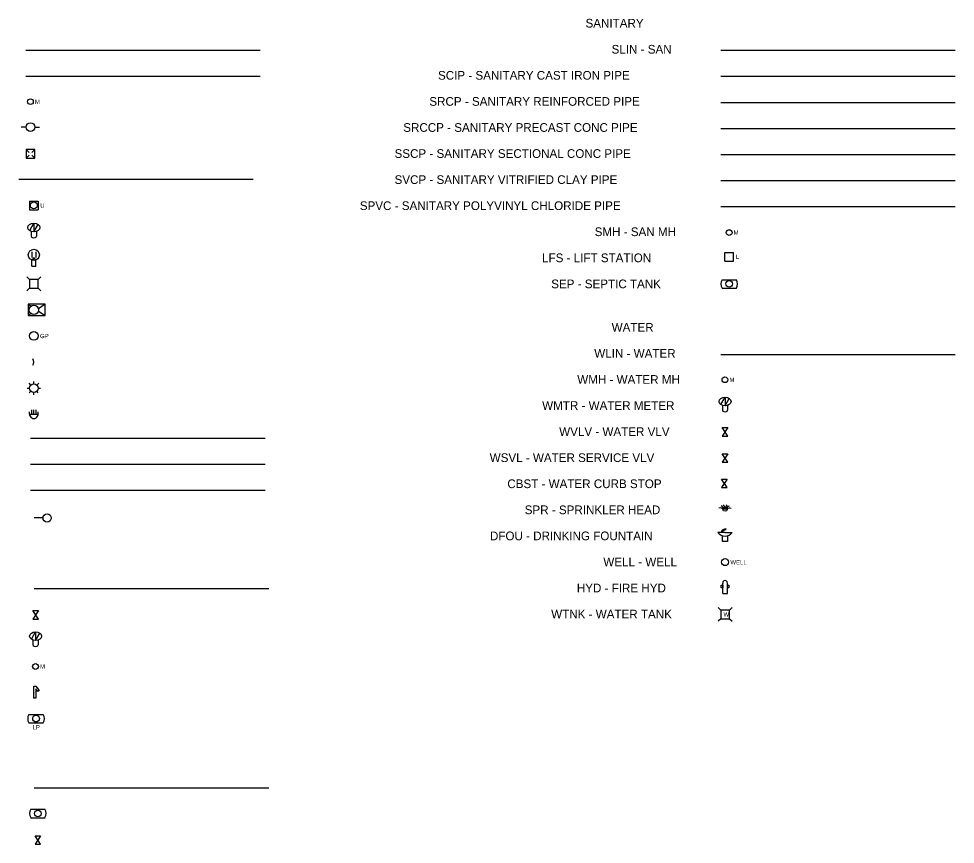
# Model space of a CAD drawing. Extents: x 2147097 to 2149342, y 2146141 to 2147624.
# Drawn here: x 2148264 to 2149342, y 2146471 to 2147421 of the extents above; entities that cross this region are included whole.
import ezdxf

# ---------------------------------------------------------------- set-up
doc = ezdxf.new("R2010")
doc.units = 0
for name, color, linetype in [('Default', 7, 'Continuous'), ('GAS LIN INP', 7, 'Continuous'), ('GAS PT INP', 7, 'Continuous'), ('PET LIN INP', 7, 'Continuous'), ('PET PT INP', 7, 'Continuous'), ('PWR LIN INP', 7, 'Continuous'), ('PWR LIN OVHD INP', 7, 'Continuous'), ('PWR PT INP', 7, 'Continuous'), ('SAN LIN INP', 7, 'Continuous'), ('SAN PT INP', 7, 'Continuous'), ('WTR LIN INP', 7, 'Continuous'), ('WTR PT INP', 7, 'Continuous')]:
    doc.layers.add(name, color=color, linetype=linetype)

msp = doc.modelspace()

# ---------------------------------------------------------------- linework, layer by layer
at = {"layer": 'GAS LIN INP'}
msp.add_line((2148281.3, 2146765.8), (2148551.3, 2146765.8), dxfattribs=at)
at = {"layer": 'GAS PT INP'}
for p, q in [((2148279.8, 2146740.3), (2148286.2, 2146740.3)), ((2148286.2, 2146730.5), (2148279.8, 2146740.3)), ((2148286.2, 2146740.3), (2148279.8, 2146730.5)), ((2148283, 2146735.4), (2148283, 2146735.4)), ((2148283, 2146735.4), (2148283, 2146735.4)), ((2148279.8, 2146730.5), (2148286.2, 2146730.5)), ((2148278.2, 2146707.5), (2148283, 2146715.8)), ((2148283, 2146715.8), (2148283, 2146706)), ((2148283, 2146706), (2148287.9, 2146714.4)), ((2148280, 2146706.5), (2148280, 2146700.9)), ((2148286, 2146706.5), (2148286, 2146700.9)), ((2148282, 2146646.2), (2148282, 2146646.2)), ((2148275.2, 2146620.8), (2148291.8, 2146620.8)), ((2148283.5, 2146616), (2148283.5, 2146616)), ((2148275.2, 2146611.1), (2148291.8, 2146611.1))]:
    msp.add_line(p, q, dxfattribs=at)
msp.add_lwpolyline([(2148281, 2146639.6), (2148281, 2146653.2), (2148283.4, 2146653.2), (2148287, 2146648.2), (2148285.5, 2146647.1), (2148283.2, 2146650.2), (2148283.2, 2146639.6)], close=True, dxfattribs=at)
for centre, radius in [((2148282.9, 2146676), 3.31), ((2148283.5, 2146616), 3.83)]:
    msp.add_circle(centre, radius, dxfattribs=at)
for centre, start, end in [((2148283, 2146616), 148.1092, 211.8908), ((2148284, 2146616), 328.1092, 31.8908)]:
    msp.add_arc(centre, 9.11, start, end, dxfattribs=at)
msp.add_ellipse((2148283, 2146710.9), major_axis=(-6.9, 0), ratio=0.710145, dxfattribs=at)
msp.add_ellipse((2148283, 2146700.9), major_axis=(-3, 0), ratio=0.602742, start_param=0, end_param=3.141593, dxfattribs=at)
at = {"layer": 'PET LIN INP'}
msp.add_line((2148281.5, 2146536.2), (2148551.5, 2146536.2), dxfattribs=at)
at = {"layer": 'PET PT INP'}
for p, q in [((2148277.3, 2146511.7), (2148293.9, 2146511.7)), ((2148285.6, 2146506.9), (2148285.6, 2146506.9)), ((2148277.3, 2146502), (2148293.9, 2146502)), ((2148282.4, 2146481.2), (2148288.8, 2146481.2)), ((2148288.8, 2146471.4), (2148282.4, 2146481.2)), ((2148288.8, 2146481.2), (2148282.4, 2146471.4)), ((2148285.6, 2146476.3), (2148285.6, 2146476.3)), ((2148285.6, 2146476.3), (2148285.6, 2146476.3)), ((2148282.4, 2146471.4), (2148288.8, 2146471.4))]:
    msp.add_line(p, q, dxfattribs=at)
msp.add_circle((2148285.6, 2146506.9), 3.83, dxfattribs=at)
for centre, start, end in [((2148285.1, 2146506.9), 148.1092, 211.8908), ((2148286.1, 2146506.9), 328.1092, 31.8908)]:
    msp.add_arc(centre, 9.11, start, end, dxfattribs=at)
at = {"layer": 'PWR LIN INP'}
for p, q in [((2148271.6, 2147385.2), (2148541.6, 2147385.2)), ((2148263.6, 2147236.8), (2148533.6, 2147236.8)), ((2148277.1, 2146938.9), (2148547.1, 2146938.9)), ((2148277.1, 2146908.9), (2148547.1, 2146908.9)), ((2148277.1, 2146878.9), (2148547.1, 2146878.9))]:
    msp.add_line(p, q, dxfattribs=at)
at = {"layer": 'PWR LIN OVHD INP'}
msp.add_line((2148271.6, 2147355.2), (2148541.6, 2147355.2), dxfattribs=at)
at = {"layer": 'PWR PT INP'}
for p, q in [((2148272.1, 2147296.8), (2148266.5, 2147296.8)), ((2148282.1, 2147296.8), (2148287.7, 2147296.8)), ((2148272.1, 2147270.9), (2148275.6, 2147267.4)), ((2148272.1, 2147260.9), (2148275.6, 2147264.4)), ((2148277.1, 2147265.9), (2148277.1, 2147265.9)), ((2148278.6, 2147267.4), (2148282.1, 2147270.9)), ((2148278.6, 2147264.4), (2148282.1, 2147260.9)), ((2148281, 2147206.6), (2148281, 2147206.6)), ((2148276.2, 2147177.9), (2148281, 2147186.2)), ((2148281, 2147186.2), (2148281, 2147176.4)), ((2148278, 2147176.9), (2148278, 2147171.3)), ((2148281, 2147176.4), (2148285.9, 2147184.8)), ((2148284, 2147176.9), (2148284, 2147171.3)), ((2148278.6, 2147153.3), (2148278.6, 2147146.5)), ((2148278.6, 2147136.7), (2148278.6, 2147143.8)), ((2148283.4, 2147153.3), (2148283.4, 2147146.5)), ((2148283.4, 2147136.7), (2148283.4, 2147143.8)), ((2148278.6, 2147136.7), (2148283.4, 2147136.7)), ((2148273, 2147124.4), (2148276, 2147121.4)), ((2148289, 2147124.4), (2148286, 2147121.4)), ((2148276, 2147111.4), (2148273, 2147108.4)), ((2148281, 2147116.4), (2148281, 2147116.4)), ((2148286, 2147111.4), (2148289, 2147108.4)), ((2148274.5, 2147092.9), (2148277.8, 2147090.7)), ((2148294, 2147092.9), (2148286.2, 2147087.7)), ((2148277.8, 2147082.1), (2148274.5, 2147079.9)), ((2148286.2, 2147085.1), (2148294, 2147079.9)), ((2148281, 2147001.4), (2148281, 2147004)), ((2148273.4, 2146996.4), (2148276, 2146996.4)), ((2148277.5, 2146999.9), (2148275.5, 2147002)), ((2148275.5, 2146990.8), (2148277.5, 2146992.9)), ((2148281, 2146996.4), (2148281, 2146996.4)), ((2148284.5, 2146999.9), (2148286.6, 2147002)), ((2148286.1, 2146990.8), (2148284.5, 2146992.9)), ((2148286.1, 2146996.4), (2148288.6, 2146996.4)), ((2148281, 2146988.8), (2148281, 2146991.4)), ((2148278.5, 2146966.4), (2148278.5, 2146971.4)), ((2148281, 2146966.4), (2148281, 2146971.4)), ((2148283.5, 2146966.4), (2148283.5, 2146971.4)), ((2148276, 2146966.4), (2148276, 2146968.9)), ((2148276, 2146966.4), (2148286, 2146966.4)), ((2148281, 2146966.4), (2148281, 2146966.4)), ((2148286, 2146966.4), (2148286, 2146968.9)), ((2148291.5, 2146846.9), (2148281.3, 2146846.9))]:
    msp.add_line(p, q, dxfattribs=at)
for points in [[(2148272.1, 2147260.9), (2148282.1, 2147260.9), (2148282.1, 2147270.9), (2148272.1, 2147270.9)], [(2148276, 2147111.4), (2148286, 2147111.4), (2148286, 2147121.4), (2148276, 2147121.4)], [(2148274.5, 2147079.9), (2148294, 2147079.9), (2148294, 2147092.9), (2148274.5, 2147092.9)]]:
    msp.add_lwpolyline(points, close=True, dxfattribs=at)
for points in [[(2148276, 2147211.6), (2148286, 2147211.6)], [(2148276, 2147211.6), (2148276, 2147201.6)], [(2148286, 2147211.6), (2148286, 2147201.6)], [(2148276, 2147201.6), (2148286, 2147201.6)]]:
    msp.add_lwpolyline(points, dxfattribs=at)
for centre, radius in [((2148277.1, 2147326), 3.31), ((2148277.1, 2147296.8), 5), ((2148281, 2147206.6), 4.01), ((2148281, 2147149.7), 6.39), ((2148281, 2147145.5), 0.9), ((2148281, 2147086.4), 5.4), ((2148281, 2147056.4), 5), ((2148281, 2146996.4), 5), ((2148296.3, 2146846.9), 4.76)]:
    msp.add_circle(centre, radius, dxfattribs=at)
for centre, radius, start, end in [((2148274.7, 2147026.3), 6.29, 324.6924, 35.1858), ((2148281, 2146966.4), 5, 179.996, 0.004)]:
    msp.add_arc(centre, radius, start, end, dxfattribs=at)
msp.add_ellipse((2148281, 2147181.3), major_axis=(-6.9, 0), ratio=0.710145, dxfattribs=at)
msp.add_ellipse((2148281, 2147171.3), major_axis=(-3, 0), ratio=0.602742, start_param=0, end_param=3.141593, dxfattribs=at)
at = {"layer": 'SAN LIN INP'}
for p, q in [((2149071.6, 2147385.2), (2149341.6, 2147385.2)), ((2149071.6, 2147355.2), (2149341.6, 2147355.2)), ((2149071.6, 2147325.2), (2149341.6, 2147325.2)), ((2149071.6, 2147295.2), (2149341.6, 2147295.2)), ((2149071.6, 2147265.2), (2149341.6, 2147265.2)), ((2149071.6, 2147235.2), (2149341.6, 2147235.2)), ((2149071.6, 2147205.2), (2149341.6, 2147205.2))]:
    msp.add_line(p, q, dxfattribs=at)
at = {"layer": 'SAN PT INP'}
for p, q in [((2149076.4, 2147142.5), (2149076.4, 2147152.5)), ((2149076.4, 2147152.5), (2149086.4, 2147152.5)), ((2149081.4, 2147147.5), (2149081.4, 2147147.5)), ((2149086.4, 2147142.5), (2149086.4, 2147152.5)), ((2149076.4, 2147142.5), (2149086.4, 2147142.5)), ((2149073.1, 2147121.1), (2149089.7, 2147121.1)), ((2149073.1, 2147111.4), (2149089.7, 2147111.4)), ((2149081.4, 2147116.3), (2149081.4, 2147116.3))]:
    msp.add_line(p, q, dxfattribs=at)
for centre, radius in [((2149081.3, 2147175.3), 3.31), ((2149081.4, 2147116.3), 3.83)]:
    msp.add_circle(centre, radius, dxfattribs=at)
for centre, start, end in [((2149080.9, 2147116.3), 148.1092, 211.8908), ((2149081.9, 2147116.3), 328.1092, 31.8908)]:
    msp.add_arc(centre, 9.11, start, end, dxfattribs=at)
at = {"layer": 'WTR LIN INP'}
msp.add_line((2149071.6, 2147035.2), (2149341.6, 2147035.2), dxfattribs=at)
at = {"layer": 'WTR PT INP'}
for p, q in [((2149071.8, 2146977.5), (2149076.6, 2146985.8)), ((2149076.6, 2146985.8), (2149076.6, 2146976)), ((2149076.6, 2146976), (2149081.5, 2146984.4)), ((2149073.6, 2146976.5), (2149073.6, 2146970.9)), ((2149079.6, 2146976.5), (2149079.6, 2146970.9)), ((2149073.4, 2146950.9), (2149079.8, 2146950.9)), ((2149079.8, 2146941.1), (2149073.4, 2146950.9)), ((2149079.8, 2146950.9), (2149073.4, 2146941.1)), ((2149073.4, 2146941.1), (2149079.8, 2146941.1)), ((2149076.6, 2146946), (2149076.6, 2146946)), ((2149076.6, 2146946), (2149076.6, 2146946)), ((2149073.4, 2146920.9), (2149079.8, 2146920.9)), ((2149079.8, 2146911.1), (2149073.4, 2146920.9)), ((2149079.8, 2146920.9), (2149073.4, 2146911.1)), ((2149073.4, 2146911.1), (2149079.8, 2146911.1)), ((2149076.6, 2146916), (2149076.6, 2146916)), ((2149076.6, 2146916), (2149076.6, 2146916)), ((2149072.7, 2146891.7), (2149079.1, 2146891.7)), ((2149079.1, 2146881.9), (2149072.7, 2146891.7)), ((2149079.1, 2146891.7), (2149072.7, 2146881.9)), ((2149075.9, 2146886.8), (2149075.9, 2146886.8)), ((2149075.9, 2146886.8), (2149075.9, 2146886.8)), ((2149072.7, 2146881.9), (2149079.1, 2146881.9)), ((2149073.7, 2146830.3), (2149068.4, 2146830.3)), ((2149076.6, 2146830.3), (2149073.7, 2146830.3)), ((2149076.6, 2146830.3), (2149084.8, 2146830.3)), ((2149073.9, 2146759.9), (2149073.9, 2146772)), ((2149076.6, 2146766), (2149076.6, 2146766)), ((2149079.3, 2146759.9), (2149079.3, 2146772)), ((2149073.9, 2146759.9), (2149079.3, 2146759.9)), ((2149068.7, 2146744), (2149071.7, 2146741)), ((2149084.7, 2146744), (2149081.7, 2146741)), ((2149071.7, 2146731), (2149068.7, 2146728)), ((2149081.7, 2146731), (2149084.7, 2146728))]:
    msp.add_line(p, q, dxfattribs=at)
msp.add_lwpolyline([(2149079.3, 2146826.4), (2149079.3, 2146819.9), (2149073.7, 2146819.9), (2149073.7, 2146826.5)], dxfattribs=at)
for points in [[(2149072.2, 2146769.6), (2149073.9, 2146769.6), (2149073.9, 2146766.6), (2149072.2, 2146766.6)], [(2149079.3, 2146769.6), (2149081, 2146769.6), (2149081, 2146766.6), (2149079.3, 2146766.6)], [(2149071.7, 2146731), (2149081.7, 2146731), (2149081.7, 2146741), (2149071.7, 2146741)]]:
    msp.add_lwpolyline(points, close=True, dxfattribs=at)
for centre, radius in [((2149076.5, 2147006), 3.31), ((2149076.6, 2146796.1), 4)]:
    msp.add_circle(centre, radius, dxfattribs=at)
for centre, radius, start, end in [((2149071.1, 2146854.3), 4.14, 33.0728, 112.242), ((2149070.9, 2146856.5), 4.34, 5.7969, 75.931), ((2149065.6, 2146857.3), 10.6, 359.6115, 27.6011), ((2149087.6, 2146856.5), 10.6, 148.3989, 176.3885), ((2149082.1, 2146856.3), 4.34, 100.069, 170.2031), ((2149081.8, 2146854.2), 4.14, 63.7581, 142.9272), ((2149076.6, 2146835.9), 9.92, 214.2578, 325.7422), ((2149078, 2146827.7), 6.62, 92.1833, 154.6964), ((2149078, 2146827.7), 6.12, 92.1833, 154.6964), ((2149078, 2146827.7), 5.62, 92.1833, 154.6964), ((2149076.6, 2146772.3), 2.71, 355.2178, 184.7822)]:
    msp.add_arc(centre, radius, start, end, dxfattribs=at)
for centre, major_axis, ratio in [((2149076.6, 2146980.9), (-6.9, 0), 0.710145), ((2149076.6, 2146856), (-2.29, -0.02), 0.553416)]:
    msp.add_ellipse(centre, major_axis=major_axis, ratio=ratio, dxfattribs=at)
msp.add_ellipse((2149076.6, 2146970.9), major_axis=(-3, 0), ratio=0.602742, start_param=0, end_param=3.141593, dxfattribs=at)

# ---------------------------------------------------------------- texts
at = {"layer": 'Default'}
for s, p in [('SANITARY', (2148916, 2147411.3)), ('SLIN - SAN', (2148946, 2147381.3)), ('SCIP - SANITARY CAST IRON PIPE', (2148746.2, 2147351.3)), ('SRCP - SANITARY REINFORCED PIPE', (2148736.2, 2147321.3)), ('SRCCP - SANITARY PRECAST CONC PIPE', (2148706.2, 2147291.3)), ('SSCP - SANITARY SECTIONAL CONC PIPE', (2148696.2, 2147261.3)), ('SVCP - SANITARY VITRIFIED CLAY PIPE', (2148696.2, 2147231.3)), ('SPVC - SANITARY POLYVINYL CHLORIDE PIPE', (2148656.2, 2147201.3)), ('SMH - SAN MH', (2148926.5, 2147171.3)), ('LFS - LIFT STATION', (2148866, 2147141.3)), ('SEP - SEPTIC TANK', (2148876.5, 2147111.3)), ('WATER', (2148946.1, 2147061.3)), ('WLIN - WATER', (2148926.1, 2147031.3)), ('WMH - WATER MH', (2148906.5, 2147001.3)), ('WMTR - WATER METER', (2148866.1, 2146971.3)), ('WVLV - WATER VLV', (2148885.7, 2146941.3)), ('WSVL - WATER SERVICE VLV', (2148805.7, 2146911.3)), ('CBST - WATER CURB STOP', (2148826, 2146881.3)), ('SPR - SPRINKLER HEAD', (2148846, 2146851.3)), ('DFOU - DRINKING FOUNTAIN', (2148806, 2146821.3)), ('WELL - WELL', (2148936.5, 2146791.3)), ('HYD - FIRE HYD', (2148906, 2146761.3)), ('WTNK - WATER TANK', (2148876.5, 2146731.3))]:
    msp.add_text(s, height=10, dxfattribs=at).set_placement(p)
at = {"layer": 'GAS PT INP'}
for s, p in [('M', (2148288.1, 2146673.5)), ('LP', (2148279.5, 2146603.6))]:
    msp.add_text(s, height=5, dxfattribs=at).set_placement(p)
at = {"layer": 'PWR PT INP'}
for s, p in [('M', (2148282.2, 2147323.5)), ('U', (2148288.4, 2147204)), ('GP', (2148288.1, 2147053.8))]:
    msp.add_text(s, height=5, dxfattribs=at).set_placement(p)
at = {"layer": 'SAN PT INP'}
for s, p in [('M', (2149086.5, 2147172.8)), ('L', (2149089.1, 2147145))]:
    msp.add_text(s, height=5, dxfattribs=at).set_placement(p)
at = {"layer": 'WTR PT INP'}
for s, p in [('M', (2149081.7, 2147003.5)), ('WELL', (2149082.7, 2146793.5)), ('W', (2149074.8, 2146733.5))]:
    msp.add_text(s, height=5, dxfattribs=at).set_placement(p)

doc.saveas('drawing.dxf')
